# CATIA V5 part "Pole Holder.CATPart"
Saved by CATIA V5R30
Part number: Pole Holder
Bounding box of the stored display mesh (mm): x -41 to 41, y -41 to 41, z 0 to 19
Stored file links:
  D:\OneDrive\OneDrive - Carleton University\Courses\aero2001\Design Project\3D Models\Closed\Pole Holder.CATPart
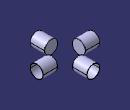
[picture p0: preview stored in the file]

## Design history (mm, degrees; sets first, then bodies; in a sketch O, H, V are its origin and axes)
Body1 (main body)
  Point1: (0, 0, 0)
  Line1: type Normal, RefPoint Point1, RefSkin xy-plane, Start 0, End 20
  Plane1: type Offset, RefPlane zx-plane, Offset 20
  Sketch1 on Plane1, origin (0, 20, 0), H (-1, 0, 0), V (0, 0, 1)
    circle A1 centre (0, 9.5) radius 9.5
    point P1 (0, 9.5)
    reference projected point E1 (0, 0) from Point1
    radius A1 = 9.5
    coincidence: P1 V, A1 E1
  Pad1: profile Sketch1, direction (0, 1, 0), length 1
  Sketch2 on end face of Pad1, origin (0, 21, 0), H (-1, 0, 0), V (0, 0, 1)
    circle A1 centre (0, 9.5) radius 9.5
    point P1 (0, 9.5)
    reference projected point E1 (0, 0) from Point1
    circle A2 centre (0, 9.5) radius 9
    radius A1 = 9.5
    radius A2 = 9
    coincidence: P1 V, A1 E1
  Pad2: profile Sketch2, direction (0, 1, 0), length 20
  CircPattern1: of the body so far, instances 4, angular step 90 {= 360.0*1 deg/CircPattern1.AngularNumber}, axis from Line1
